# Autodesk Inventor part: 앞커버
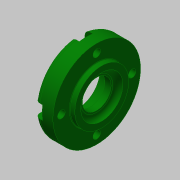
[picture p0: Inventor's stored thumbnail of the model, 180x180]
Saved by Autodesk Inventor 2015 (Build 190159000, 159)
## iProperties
Created: 2015-11
Part Number: 앞커버
Material: 알루미늄 6061
Document SubType Name: Modeling
Designer: mduedu
Density: 1 g/cm^3
Appearance: 진녹색
Author: mduedu
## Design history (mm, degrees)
sketch "스케치1"
  geometry: L1 (-7, 0)-(7, 0); L2 (-7, 0)-(-7, 26); L3 (-7, 26)-(4, 26); L4 (4, 26)-(4, 16); L5 (4, 16)-(7, 16); L6 (7, 16)-(7, 0); 2 further points
  constraints: 12 end point, 3 perpendicular, 2 parallel, 1 coincident, 1 horizontal, 1 midpoint
  dimensions: "d0" = 14 distance of L1.start L1.end; "d1" = 52 diameter of L3 L1; "d2" = 3 distance of L4.end L5.end; "d3" = 32 diameter of L5 L1
revolve "회전1" sketch "스케치1" stored, may be unused: angle "d4" = 90 deg
hole "구멍1" diameter "d7" = 25; stored, may be unused: countersink angle "d11" = 90 deg, drill point angle "d13" = 0 deg; dims "d5" = 10, "d6" = 10, "d8" = 6, "d9" = 4, "d10" = 2, "d12" = 3
hole "구멍2" diameter "d16" = 25; stored, may be unused: countersink angle "d20" = 90 deg, drill point angle "d22" = 0 deg; dims "d17" = 6, "d18" = 4, "d19" = 2, "d21" = 7.3, "d62" = 10, "d63" = 10
hole "구멍3" diameter "d25" = 17; stored, may be unused: countersink angle "d29" = 90 deg, drill point angle "d31" = 0 deg; dims "d23" = 10, "d24" = 10, "d26" = 6, "d27" = 4, "d28" = 2, "d30" = 4.2
chamfer "모따기1" distance "d32" = 0.7; stored, may be unused: second distance "d33" = 2, angle "d34" = 30 deg
fillet "모깎기1" dims "d35" = 0.3
fillet "모깎기2" dims "d36" = 3
fillet "모깎기3" dims "d37" = 3
fillet "모깎기4" dims "d38" = 0.3
sketch "스케치3" dims "d61" = 42
  geometry: C1 r 26 at (0, 0) reference; 2 further points
  constraints: 2 vertical alignment, 1 coincident, 2 other
hole "구멍4" sketch "스케치3" at (0, -21) diameter "d44" = 4.5; stored, may be unused: countersink angle "d48" = 90 deg, drill point angle "d50" = 0 deg; dims "d45" = 6, "d46" = 8, "d47" = 4.6, "d49" = 8
sketch "스케치4"
  geometry: L1 (-4, 0)-(-4, -4.69); L2 (4, 0)-(4, -4.69); A1 r 4 centre (0, 0) between (3.614, -1.714) and (-3.614, -1.714) reference; A2 r 26 centre (0, 21) between (-4, -4.69) and (4, -4.69) reference; 1 further point
  constraints: 4 end point, 4 point on circle, 2 tangent, 1 parallel, 1 vertical
extrude "돌출1" cut sketch "스케치4" stored distance "d51" = 0; taper "d52" = 0 deg
node "솔리드1"
pattern_circular "원형 패턴1" dims angle "d54" = 360 deg
